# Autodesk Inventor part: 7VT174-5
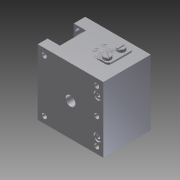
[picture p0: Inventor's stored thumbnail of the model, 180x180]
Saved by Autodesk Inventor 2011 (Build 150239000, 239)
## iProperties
Created: 2011-04
Part Number: 7VT174-5
Document SubType Name: Modeling
Designer: vadybininkas6
Density: 1 g/cm^3
Author: vadybininkas6
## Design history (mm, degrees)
feature "Base1"
body "Solid1"
